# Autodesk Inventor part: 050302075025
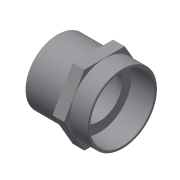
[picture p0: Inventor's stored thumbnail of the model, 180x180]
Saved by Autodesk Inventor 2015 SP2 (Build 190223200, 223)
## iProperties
Created: 2017-10
Part Number: 050302075025
Material: Generic
Description: PLASSON ADAPTOR SOCKET M.F. 75-2.1/2" CEM-THR
Document SubType Name: Modeling
Designer: KIM
Density: 1 g/cm^3
Appearance: Default
Author: KIM
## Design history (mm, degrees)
derived "050302.ipt"
feature "Solid1::050302.ipt"
tag "TaggingFeature1"
body "Solid1"
other parameters: "d0" = 87, "d3" = 72.226, "d4" = 52.5, "d6" = 29, "d8" = 78.75, "d13" = 0, "d14" = 0.75, "d17" = 44, "d18" = 34.8, "d19" = 75, "d_" = 75, "G_" = 72.226, "L_" = 44, "lt_" = 29, "H_" = 87
